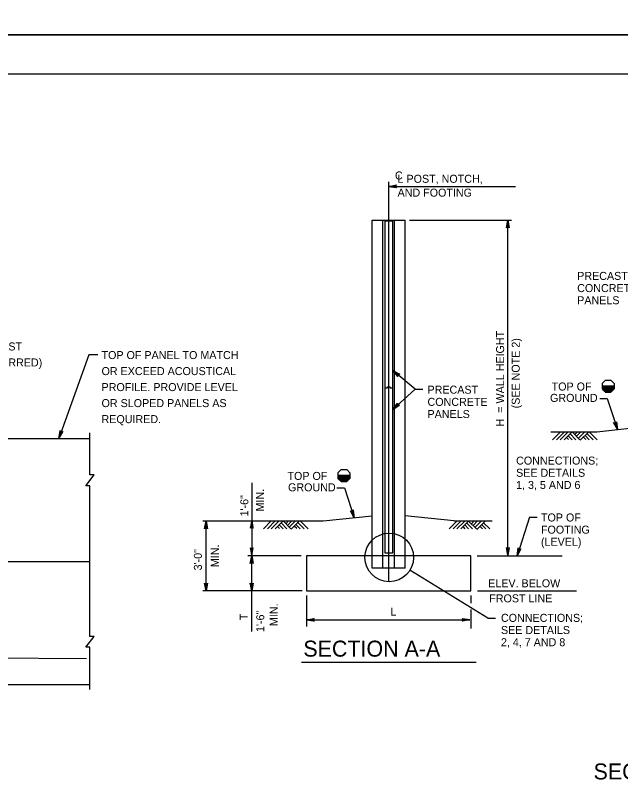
# Model space of a CAD drawing. Extents: x 3351 to 8430, y -3586 to 1457.
# Drawn here: x 4252.5 to 4484.6, y 284.8 to 579.2 of the extents above; entities that cross this region are included whole.
import ezdxf

# ---------------------------------------------------------------- set-up
doc = ezdxf.new("R2010")
doc.units = 0
for name, color, linetype in [('1', 7, 'Continuous'), ('2', 7, 'Continuous'), ('PLT-BNDY', 7, 'Continuous')]:
    doc.layers.add(name, color=color, linetype=linetype)

msp = doc.modelspace()

# ---------------------------------------------------------------- linework, layer by layer
at = {"layer": '1'}
for p, q in [((4395.74, 362.03), (4395.74, 515.35)), ((4395.74, 513.59), (4444.29, 513.59)), ((4389.28, 371.89), (4389.28, 500.6)), ((4389.28, 500.6), (4402.03, 500.6)), ((4393.4, 371.89), (4393.4, 500.6)), ((4397.9, 371.89), (4397.9, 500.6)), ((4402.03, 371.89), (4402.03, 500.6)), ((4403.67, 500.6), (4442.76, 500.6)), ((4441.35, 372.02), (4441.35, 500.6)), ((4394.24, 462.97), (4394.24, 436.25)), ((4280.69, 448.88), (4269.23, 416.9)), ((4284.1, 448.88), (4280.69, 448.88)), ((4405.87, 435.75), (4397.24, 442.95)), ((4478.74, 439.24), (4477.49, 437.99)), ((4478.74, 439.24), (4480.86, 439.24)), ((4480.86, 439.24), (4482.11, 437.99)), ((4394.24, 436.25), (4394.24, 372.97)), ((4395.26, 436.25), (4395.26, 436.73)), ((4395.26, 436.73), (4396.22, 436.73)), ((4396.22, 436.25), (4396.22, 436.73)), ((4397.24, 372.97), (4397.24, 436.25)), ((4405.87, 435.75), (4397.24, 428)), ((4405.87, 435.75), (4408.77, 435.75)), ((4477.48, 437.05), (4482.1, 437.05)), ((4477.48, 436.05), (4482.1, 436.05)), ((4477.48, 435.95), (4482.1, 435.95)), ((4477.49, 437.99), (4477.49, 435.87)), ((4477.49, 436.55), (4482.1, 436.55)), ((4477.49, 436.45), (4482.1, 436.45)), ((4477.49, 436.35), (4482.1, 436.35)), ((4477.49, 436.25), (4482.1, 436.25)), ((4477.49, 436.15), (4482.1, 436.15)), ((4478.74, 434.62), (4477.49, 435.87)), ((4477.5, 436.95), (4482.1, 436.95)), ((4477.5, 436.85), (4482.1, 436.85)), ((4477.5, 436.75), (4482.1, 436.75)), ((4477.5, 436.65), (4482.1, 436.65)), ((4477.5, 435.85), (4482.06, 435.85)), ((4477.6, 435.75), (4481.96, 435.75)), ((4480.59, 437.05), (4482.1, 437.05)), ((4480.86, 434.62), (4482.11, 435.87)), ((4482.11, 437.99), (4482.11, 435.87)), ((4477.7, 435.65), (4481.86, 435.65)), ((4477.81, 435.55), (4481.77, 435.55)), ((4477.91, 435.45), (4481.67, 435.45)), ((4478.01, 435.35), (4481.57, 435.35)), ((4478.11, 435.25), (4481.48, 435.25)), ((4478.21, 435.15), (4481.38, 435.15)), ((4478.32, 435.05), (4481.29, 435.05)), ((4478.42, 434.95), (4481.19, 434.95)), ((4478.52, 434.85), (4481.09, 434.85)), ((4478.62, 434.75), (4481, 434.75)), ((4478.72, 434.65), (4480.9, 434.65)), ((4478.74, 434.62), (4480.86, 434.62)), ((4476.58, 432.24), (4479.48, 432.24)), ((4479.48, 432.24), (4483.34, 420.28)), ((4475.47, 419.45), (4494.14, 421.41)), ((4281.14, 402.85), (4281.14, 419.06)), ((4457.84, 419.45), (4475.47, 419.45)), ((4458.46, 416.39), (4461.53, 419.45)), ((4459.96, 416.39), (4463.03, 419.45)), ((4461.46, 416.39), (4464.53, 419.45)), ((4462.96, 416.39), (4466.03, 419.45)), ((4467.47, 416.39), (4465.21, 418.64)), ((4468.97, 416.39), (4465.96, 419.39)), ((4468.12, 419.45), (4466.99, 418.33)), ((4469.38, 419.45), (4467.64, 417.71)), ((4470.88, 419.45), (4468.39, 416.96)), ((4472.38, 419.45), (4469.14, 416.21)), ((4474.06, 416.39), (4471.69, 418.75)), ((4475.56, 416.39), (4472.49, 419.45)), ((4239.01, 416.9), (4280.81, 416.9)), ((4464.64, 416.44), (4463.82, 417.27)), ((4465.97, 416.39), (4464.46, 417.89)), ((4471.23, 416.44), (4470.3, 417.37)), ((4472.56, 416.39), (4470.94, 418)), ((4377.46, 404.93), (4376.21, 403.68)), ((4376.21, 403.68), (4376.21, 401.56)), ((4377.46, 404.93), (4379.57, 404.93)), ((4379.57, 404.93), (4380.83, 403.68)), ((4380.83, 403.68), (4380.83, 401.56)), ((4376.19, 402.74), (4380.81, 402.74)), ((4376.2, 401.94), (4380.81, 401.94)), ((4376.2, 401.84), (4380.81, 401.84)), ((4376.2, 401.74), (4380.81, 401.74)), ((4376.2, 401.64), (4380.81, 401.64)), ((4376.21, 402.44), (4380.81, 402.44)), ((4376.21, 402.34), (4380.81, 402.34)), ((4376.21, 402.24), (4380.81, 402.24)), ((4376.21, 402.14), (4380.81, 402.14)), ((4376.21, 402.04), (4380.81, 402.04)), ((4377.46, 400.31), (4376.21, 401.56)), ((4376.22, 402.64), (4380.81, 402.64)), ((4376.22, 402.54), (4380.81, 402.54)), ((4376.22, 401.54), (4380.77, 401.54)), ((4376.32, 401.44), (4380.67, 401.44)), ((4376.42, 401.34), (4380.58, 401.34)), ((4376.52, 401.24), (4380.48, 401.24)), ((4376.62, 401.14), (4380.39, 401.14)), ((4376.73, 401.04), (4380.29, 401.04)), ((4376.83, 400.94), (4380.19, 400.94)), ((4376.93, 400.84), (4380.1, 400.84)), ((4377.03, 400.74), (4380, 400.74)), ((4377.13, 400.64), (4379.91, 400.64)), ((4377.23, 400.54), (4379.81, 400.54)), ((4377.34, 400.44), (4379.71, 400.44)), ((4379.3, 402.74), (4380.81, 402.74)), ((4379.57, 400.31), (4380.83, 401.56)), ((4281.14, 340.9), (4281.14, 398.67)), ((4343.18, 399.78), (4343.18, 371.92)), ((4375.81, 397.93), (4378.71, 397.93)), ((4377.44, 400.34), (4379.62, 400.34)), ((4377.46, 400.31), (4379.57, 400.31)), ((4378.71, 397.93), (4382.41, 386.44)), ((4370.61, 385.2), (4389.28, 387.16)), ((4420.69, 385.2), (4402.03, 387.16)), ((4449.7, 386.69), (4444.92, 371.89)), ((4449.7, 386.69), (4452.6, 386.69)), ((4324.46, 385.2), (4370.61, 385.2)), ((4325.63, 358.39), (4325.63, 385.2)), ((4347.65, 382.2), (4350.65, 385.2)), ((4349.15, 382.2), (4352.15, 385.2)), ((4350.65, 382.2), (4353.65, 385.2)), ((4352.15, 382.2), (4355.15, 385.2)), ((4353.82, 382.26), (4353, 383.08)), ((4355.15, 382.2), (4353.65, 383.7)), ((4356.65, 382.2), (4354.4, 384.45)), ((4358.15, 382.2), (4355.15, 385.2)), ((4357.23, 385.2), (4356.18, 384.14)), ((4358.5, 385.2), (4356.82, 383.52)), ((4360, 385.2), (4357.57, 382.77)), ((4361.5, 385.2), (4358.32, 382.02)), ((4360.41, 382.26), (4359.59, 383.08)), ((4361.74, 382.2), (4360.24, 383.7)), ((4363.24, 382.2), (4360.99, 384.45)), ((4364.74, 382.2), (4361.74, 385.2)), ((4418.83, 382.16), (4421.83, 385.16)), ((4420.33, 382.16), (4423.33, 385.16)), ((4420.69, 385.2), (4435.28, 385.2)), ((4421.83, 382.16), (4424.83, 385.16)), ((4423.33, 382.16), (4426.33, 385.16)), ((4425.01, 382.22), (4424.18, 383.04)), ((4426.33, 382.16), (4424.83, 383.66)), ((4427.83, 382.16), (4425.58, 384.41)), ((4429.33, 382.16), (4426.33, 385.16)), ((4428.47, 385.2), (4427.36, 384.1)), ((4429.73, 385.2), (4428.01, 383.48)), ((4431.23, 385.2), (4428.76, 382.73)), ((4432.73, 385.2), (4429.51, 381.98)), ((4431.6, 382.22), (4430.77, 383.04)), ((4432.92, 382.16), (4431.42, 383.66)), ((4434.42, 382.16), (4432.17, 384.41)), ((4362.09, 371.89), (4341.62, 371.89)), ((4343.18, 342.8), (4343.18, 371.86)), ((4427.15, 371.89), (4364.15, 371.89)), ((4364.15, 371.89), (4364.15, 358.39)), ((4389.28, 367.09), (4389.28, 371.89)), ((4393.4, 367.09), (4393.4, 371.89)), ((4394.24, 372.97), (4397.24, 372.97)), ((4397.9, 367.09), (4397.9, 371.89)), ((4402.03, 367.09), (4402.03, 371.89)), ((4427.15, 358.39), (4427.15, 371.89)), ((4429.63, 371.89), (4462.14, 371.89)), ((4236, 369.69), (4281.14, 369.69)), ((4402.03, 367.09), (4389.28, 367.09)), ((4433.74, 347.9), (4403.82, 366.32)), ((4362.56, 358.39), (4324.46, 358.39)), ((4364.15, 358.39), (4427.15, 358.39)), ((4364.15, 356.55), (4364.15, 344.7)), ((4427.15, 356.55), (4427.15, 353.67)), ((4429.74, 358.39), (4467.62, 358.39)), ((4427.15, 351.27), (4427.15, 343.97)), ((4433.74, 347.9), (4436.64, 347.9)), ((4364.15, 347.27), (4426.76, 347.27)), ((4281.14, 320.56), (4281.14, 336.73)), ((4362.27, 331.08), (4429.18, 331.08)), ((4239.09, 322.48), (4281.14, 322.48))]:
    msp.add_line(p, q, dxfattribs=at)
for points in [[(4395.74, 513.59), (4398.72, 514.15), (4398.49, 513.99), (4398.37, 513.79), (4398.34, 513.59), (4398.37, 513.39), (4398.49, 513.19), (4398.72, 513.03), (4395.74, 513.59), (4398.49, 513.19), (4398.37, 513.39), (4395.74, 513.59), (4398.34, 513.59), (4398.37, 513.79), (4395.74, 513.59), (4398.49, 513.99)], [(4441.35, 500.6), (4441.9, 497.62), (4441.75, 497.85), (4441.55, 497.97), (4441.35, 498), (4441.15, 497.97), (4440.95, 497.85), (4440.79, 497.62), (4441.35, 500.6), (4440.95, 497.85), (4441.15, 497.97), (4441.35, 500.6), (4441.35, 498), (4441.55, 497.97), (4441.35, 500.6), (4441.75, 497.85)], [(4397.24, 462.97), (4397.24, 500.22), (4394.24, 500.22), (4394.24, 462.97)], [(4397.24, 436.25), (4397.24, 462.97)], [(4397.24, 442.95), (4399.89, 441.47), (4399.61, 441.49), (4399.39, 441.42), (4399.23, 441.28), (4399.13, 441.11), (4399.1, 440.88), (4399.17, 440.61), (4397.24, 442.95), (4399.1, 440.88), (4399.13, 441.11), (4397.24, 442.95), (4399.23, 441.28), (4399.39, 441.42), (4397.24, 442.95), (4399.61, 441.49)], [(4394.24, 436.25), (4395.26, 436.25)], [(4396.22, 436.25), (4397.24, 436.25)], [(4397.24, 428), (4399.08, 430.41), (4399.02, 430.13), (4399.06, 429.91), (4399.17, 429.73), (4399.33, 429.61), (4399.55, 429.54), (4399.83, 429.57), (4397.24, 428), (4399.55, 429.54), (4399.33, 429.61), (4397.24, 428), (4399.17, 429.73), (4399.06, 429.91), (4397.24, 428), (4399.02, 430.13)], [(4483.34, 420.28), (4481.89, 422.94), (4482.12, 422.78), (4482.34, 422.72), (4482.54, 422.75), (4482.72, 422.85), (4482.88, 423.02), (4482.96, 423.29), (4483.34, 420.28), (4482.88, 423.02), (4482.72, 422.85), (4483.34, 420.28), (4482.54, 422.75), (4482.34, 422.72), (4483.34, 420.28), (4482.12, 422.78)], [(4269.23, 416.9), (4269.71, 419.9), (4269.78, 419.63), (4269.93, 419.45), (4270.1, 419.35), (4270.3, 419.32), (4270.53, 419.36), (4270.76, 419.52), (4269.23, 416.9), (4270.53, 419.36), (4270.3, 419.32), (4269.23, 416.9), (4270.1, 419.35), (4269.93, 419.45), (4269.23, 416.9), (4269.78, 419.63)], [(4281.14, 398.67), (4279.55, 398.67), (4282.73, 402.85), (4281.14, 402.85)], [(4382.41, 386.44), (4380.97, 389.11), (4381.19, 388.94), (4381.41, 388.89), (4381.61, 388.92), (4381.79, 389.01), (4381.95, 389.19), (4382.03, 389.45), (4382.41, 386.44), (4381.95, 389.19), (4381.79, 389.01), (4382.41, 386.44), (4381.61, 388.92), (4381.41, 388.89), (4382.41, 386.44), (4381.19, 388.94)], [(4325.63, 385.2), (4326.19, 382.22), (4326.03, 382.45), (4325.83, 382.57), (4325.63, 382.6), (4325.43, 382.57), (4325.23, 382.45), (4325.07, 382.22), (4325.63, 385.2), (4325.23, 382.45), (4325.43, 382.57), (4325.63, 385.2), (4325.63, 382.6), (4325.83, 382.57), (4325.63, 385.2), (4326.03, 382.45)], [(4343.18, 385.39), (4342.62, 382.41), (4342.78, 382.64), (4342.98, 382.75), (4343.18, 382.79), (4343.38, 382.75), (4343.58, 382.64), (4343.74, 382.41), (4343.18, 385.39), (4343.58, 382.64), (4343.38, 382.75), (4343.18, 385.39), (4343.18, 382.79), (4342.98, 382.75), (4343.18, 385.39), (4342.78, 382.64)], [(4343.18, 371.92), (4343.74, 374.9), (4343.58, 374.67), (4343.38, 374.56), (4343.18, 374.52), (4342.98, 374.56), (4342.78, 374.67), (4342.62, 374.9), (4343.18, 371.92), (4342.78, 374.67), (4342.98, 374.56), (4343.18, 371.92), (4343.18, 374.52), (4343.38, 374.56), (4343.18, 371.92), (4343.58, 374.67)], [(4441.35, 372.02), (4440.79, 375), (4440.95, 374.77), (4441.15, 374.65), (4441.35, 374.62), (4441.55, 374.65), (4441.75, 374.77), (4441.9, 375), (4441.35, 372.02), (4441.75, 374.77), (4441.55, 374.65), (4441.35, 372.02), (4441.35, 374.62), (4441.15, 374.65), (4441.35, 372.02), (4440.95, 374.77)], [(4444.92, 371.89), (4445.31, 374.9), (4445.39, 374.63), (4445.54, 374.46), (4445.72, 374.36), (4445.92, 374.33), (4446.15, 374.39), (4446.37, 374.56), (4444.92, 371.89), (4446.15, 374.39), (4445.92, 374.33), (4444.92, 371.89), (4445.72, 374.36), (4445.54, 374.46), (4444.92, 371.89), (4445.39, 374.63)], [(4343.18, 371.86), (4343.74, 368.87), (4343.58, 369.1), (4343.38, 369.22), (4343.18, 369.26), (4342.98, 369.22), (4342.78, 369.1), (4342.62, 368.87), (4343.18, 371.86), (4342.78, 369.1), (4342.98, 369.22), (4343.18, 371.86), (4343.18, 369.26), (4343.38, 369.22), (4343.18, 371.86), (4343.58, 369.1)], [(4325.63, 358.39), (4325.07, 361.37), (4325.23, 361.14), (4325.43, 361.02), (4325.63, 360.99), (4325.83, 361.02), (4326.03, 361.14), (4326.19, 361.37), (4325.63, 358.39), (4326.03, 361.14), (4325.83, 361.02), (4325.63, 358.39), (4325.63, 360.99), (4325.43, 361.02), (4325.63, 358.39), (4325.23, 361.14)], [(4343.18, 358.39), (4342.62, 361.37), (4342.78, 361.14), (4342.98, 361.02), (4343.18, 360.99), (4343.38, 361.02), (4343.58, 361.14), (4343.74, 361.37), (4343.18, 358.39), (4343.58, 361.14), (4343.38, 361.02), (4343.18, 358.39), (4343.18, 360.99), (4342.98, 361.02), (4343.18, 358.39), (4342.78, 361.14)], [(3861.98, 350.45), (3878.35, 350.9), (3891.12, 350.32), (3914.31, 351.17), (3937.57, 351.17), (3961.32, 351.07), (3966.64, 351.17), (3982.01, 351.07), (3996.76, 351.17), (4011.56, 350.95), (4046.92, 351.17), (4066.47, 350.64), (4086.26, 348.09), (4094.49, 346.67), (4106.93, 345.35), (4120.71, 343.61), (4143.22, 341.33), (4160.6, 339.19), (4243, 332.75), (4279.86, 332.38)], [(4364.15, 347.27), (4367.13, 347.83), (4366.9, 347.67), (4366.79, 347.47), (4366.75, 347.27), (4366.79, 347.07), (4366.9, 346.87), (4367.13, 346.71), (4364.15, 347.27), (4366.9, 346.87), (4366.79, 347.07), (4364.15, 347.27), (4366.75, 347.27), (4366.79, 347.47), (4364.15, 347.27), (4366.9, 347.67)], [(4426.76, 347.27), (4423.78, 346.71), (4424.01, 346.87), (4424.12, 347.07), (4424.16, 347.27), (4424.12, 347.47), (4424.01, 347.67), (4423.78, 347.83), (4426.76, 347.27), (4424.01, 347.67), (4424.12, 347.47), (4426.76, 347.27), (4424.16, 347.27), (4424.12, 347.07), (4426.76, 347.27), (4424.01, 346.87)], [(4281.14, 336.73), (4279.55, 336.73), (4282.73, 340.9), (4281.14, 340.9)]]:
    msp.add_lwpolyline(points, dxfattribs=at)
msp.add_circle((4395.87, 371.21), 9.33, dxfattribs=at)
at = {"layer": '2'}
msp.add_line((3801.34, 556.69), (4587.34, 556.69), dxfattribs=at)
at = {"layer": 'PLT-BNDY'}
for points in [[(3761.34, 1165.69), (4602.34, 1165.69), (4602.34, 571.69), (3761.34, 571.69)], [(3761.34, 571.69), (4602.34, 571.69), (4602.34, -22.31), (3761.34, -22.31)]]:
    msp.add_lwpolyline(points, close=True, dxfattribs=at)

# ---------------------------------------------------------------- texts
at = {"layer": '1'}
for s, height, p in [('C', 3.07, (4398.07, 516.22)), ('L POST, NOTCH,', 3.0721, (4399.07, 514.95)), ('AND FOOTING', 3.0721, (4399.07, 509.64)), ('PRECAST', 3.072, (4467.94, 477.69)), ('CONCRETE', 3.072, (4467.94, 473.02)), ('PANELS', 3.072, (4467.94, 468.35)), ('OPTIONAL SLOPED PRECAST', 3.072, (4195.97, 450.62)), ('TOP OF PANEL TO MATCH', 3.072, (4285.58, 447.32)), ('CONCRETE PANEL (PREFERRED)', 3.072, (4195.97, 444.48)), ('OR EXCEED ACOUSTICAL', 3.072, (4285.58, 441.17)), ('PROFILE. PROVIDE LEVEL', 3.072, (4285.58, 435.03)), ('PRECAST', 3.072, (4410.55, 434.04)), ('TOP OF', 3.072, (4458.15, 435.25)), ('GROUND', 3.072, (4457.52, 430.89)), ('OR SLOPED PANELS AS', 3.072, (4285.58, 428.89)), ('CONCRETE', 3.072, (4410.55, 429.36)), ('PANELS', 3.072, (4410.55, 424.69)), ('REQUIRED.', 3.072, (4285.58, 422.74)), ('CONNECTIONS;', 3.0721, (4444.52, 406.83)), ('TOP OF', 3.072, (4356.87, 400.95)), ('SEE DETAILS', 3.0721, (4444.52, 402.16)), ('1, 3, 5 AND 6', 3.0721, (4444.52, 397.48)), ('GROUND', 3.072, (4357.09, 396.58)), ('TOP OF', 3.072, (4454.05, 385.01)), ('FOOTING', 3.072, (4454.05, 380.34)), ('(LEVEL)', 3.072, (4454.05, 375.67)), ('ELEV. BELOW', 3.0721, (4433.82, 359.76)), ('FROST LINE', 3.072, (4434.23, 353.98)), ('L', 3, (4396.34, 348.9)), ('CONNECTIONS;', 3.0721, (4438.71, 346.5)), ('SEE DETAILS', 3.0721, (4438.71, 341.82)), ('SECTION A-A', 6.144, (4362.95, 333.15)), ('2, 4, 7 AND 8', 3.0721, (4438.71, 337.15)), ('SECTION B-B', 6.144, (4474.21, 286.03))]:
    msp.add_text(s, height=height, dxfattribs=at).set_placement(p)
for s, height, p in [('H  = WALL HEIGHT', 3.072, (4439.92, 421.49)), ('(SEE NOTE 2)', 3.072, (4445.91, 428.41)), ('1\'-6"', 3.072, (4341.86, 386.93)), ('MIN.', 3.072, (4347.81, 388.86)), ('3\'-0"', 3.072, (4324.05, 366.24)), ('MIN.', 3.072, (4330.55, 367.5)), ('1\'-6"', 3.072, (4347.96, 342.6)), ('MIN.', 3.072, (4353.16, 344.88)), ('T', 3.07, (4341.65, 347.15))]:
    msp.add_text(s, height=height, rotation=90, dxfattribs=at).set_placement(p)

doc.saveas('drawing.dxf')
